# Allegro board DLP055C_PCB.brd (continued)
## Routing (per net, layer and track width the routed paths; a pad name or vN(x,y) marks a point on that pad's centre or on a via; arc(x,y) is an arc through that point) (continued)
P3P3V_SB: length 143.3
  TOP w0.203: U27.3 34.85,72.78 C530.2 ; U17.1 9.88,94.48 v1(9.54,94.82) ; U562.23 26.33,74.76 26.54,74.56 v1(26.67,74.56) ; U561.7 33.51,83.57 33.36,83.72 v1(33.25,83.72) ; U561.3 39.23,84.07 v1(39.26,84.05) ; U27.7 40.31,73.27 v1(40.38,73.35) ; U525.1 84.51,97.5 v1(83.96,98.04) ; v1(17.84,101.22) 16.83,101.22 16.58,101.47 U559.7
  TOP w0.254: v1(25.13,111.28) 25.47,110.94 U26.50 ; v1(25.62,120.98) 25.47,121.13 U26.11 ; U562.1 v1(27.61,80.65) ; U26.18 v1(21.97,121.14)
  TOP w0.381: R623.2 v1(40.84,82.74) ; v1(167.31,50.66) 167.45,50.8 R76.2 ; D52.2 v1(4.95,128.23) ; v1(77.15,146.66) U519.3 ; v1(33.86,72.5) 33.87,72.51 C530.2 ; R611.2 v1(11.11,119.38) ; U2.5 v1(61.38,137.16) ; R607.1 v1(42.58,99.51) ; R861.2 9.7,95.89 v1(9.11,95.89) ; U563.5 33.35,81.29 v1(33.59,81.05) ; D5.2 v1(104.35,38.42) ; D10.2 v1(40.49,90.77) ; v1(81.52,93.1) 81.52,92.96 82.07,92.42 U526.1 ; U19.5 v1(98.61,35.57) ; v1(34.72,75.2) 35.29,75.77 U560.8 ; R610.2 v1(11.11,116.84) ; R862.2 v1(8.94,97.27) ; R153.1 v1(91.96,31.75) ; R598.2 v1(11.11,118.11) ; U20.5 v1(98.61,31.45) ; U42.5 v1(41.86,90.79) ; U564.5 v1(41.99,83.17) ; U33.5 165.45,51.43 v1(165.44,51.44) ; U526.4 81.87,90.46 v1(81.39,89.99) ; R597.2 v1(11.11,115.57) ; D8.2 v1(104.33,30.16) ; U13.5 v1(92.58,29.54) ; R606.1 v1(42.58,103.53) ; U565.5 v1(59.06,148.83) ; U40.5 v1(41.7,86.98) ; U18.5 v1(86.25,29.86) ; v1(161.63,49.17) 161.63,49.18 R75.1 ; U3.5 v1(73.52,137.16) ; U14.5 v1(98.6,39.7) ; D7.2 v1(104.31,34.29) ; R832.1 v1(91.33,98.6) ; R609.2 v1(11.11,114.3) ; F1.2 v1(9.84,99.75) ; R1.2 v1(74.7,148.59) ; R596.2 v1(11.11,113.03) ; D53.2 v1(40.49,87.01)
  TOP w0.635: 167.42,134.52 TP248.1 168.49,134.52
  LY7_PLANE w0.635: 6.84,148.41 J85.1 ; J85.1 9.03,146.23 ; J85.1 9.03,148.41 ; J85.1 6.84,146.23 ; J96.1 43.32,94.16 ; J96.1 41.13,94.16 ; J96.1 43.32,96.34 ; J96.1 41.13,96.34 ; 11.49,101.86 J52.1 ; J52.1 13.28,101.86 ; J52.1 11.49,100.07 ; J52.1 13.28,100.07 ; TP248.1 168.49,134.52 ; TP248.1 167.42,134.52 ; TP248.1 168.49,133.45 ; TP248.1 167.42,133.45 ; J72.1 31.69,73.92 ; J72.1 31.69,72.13 ; J72.1 29.9,72.13 ; J72.1 29.9,73.92
  BOTTOM w0.203: C515.1 17.09,101.22 v1(17.84,101.22) ; v1(40.38,73.35) 40.3,73.35 40.04,73.61 39.62,73.61 C529.1
  BOTTOM w0.254: v1(25.13,111.28) 25.13,110.43 C519.1
  BOTTOM w0.381: U520.5 v1(78.1,146.83) ; U569.5 v1(70.36,150.13) ; v1(70.36,150.13) 74.38,150.13 74.7,149.82 v1(74.7,148.59) ; v1(70.36,150.13) 70.12,150.38 66.67,150.38 v1(66.45,150.16) U568.5 ; U58.5 v1(82.55,110.61) ; v1(26.67,74.56) 26.47,74.76 C622.1 ; v1(33.25,83.72) 33.35,83.82 C548.2 ; R605.2 v1(33.97,81.92) ; R196.2 86.47,89.97 86.09,89.59 v1(85.69,89.59) ; v1(27.61,80.65) 27.6,80.64 C623.1 ; U529.5 v1(84.69,112.31) ; U558.5 v1(23.1,117.09) ; R195.2 v1(91.1,93.34) ; v1(91.33,98.6) 91.33,98.17 90.94,97.79 R193.2 ; v1(76.06,136.02) 76.05,136 R87.1 ; C549.1 21.97,121.97 v1(21.97,121.14) ; R853.2 v1(41.71,127.29) ; C547.1 39.03,83.82 v1(39.26,84.05) ; R855.2 v1(32.82,125.53) ; R592.1 v1(43.21,114.22) ; C520.2 25.62,121.93 v1(25.62,120.98) ; R854.2 v1(38.53,127.39) ; R197.2 v1(87.19,96.72) ; R628.2 v1(12.5,139.81) ; C528.2 v1(34.72,75.2) ; v1(6.76,118.51) 6.65,118.51 6.41,118.75 R612.1
  BOTTOM w0.508: v1(74.7,148.59) 72.83,146.73 72.83,137.85 v1(73.52,137.16)
  vias: v1(81.29,118.92) v1(81.29,117.91) v1(81.29,116.89) v1(81.29,115.87) v1(82.31,118.92) v1(82.31,117.91) v1(82.31,116.89) v1(82.31,115.87) v1(83.32,118.92) v1(83.32,117.91) v1(83.32,116.89) v1(83.32,115.87) v1(84.34,118.92) v1(84.34,117.91) v1(84.34,116.89) v1(84.34,115.87) v1(85.36,118.92) v1(85.36,117.91) v1(85.36,116.89) v1(85.36,115.87) v1(86.37,118.92) v1(86.37,117.91) v1(86.37,116.89) v1(86.37,115.87) v1(167.32,135.59) v1(168.82,136.19) v1(168.77,135.38)
P4.0: length 7
  TOP w0.191: U26.45 22.97,106.32 22.35,105.7 22.35,104.1 22.54,103.9 TP116.1
P4.3: length 5.3
  TOP w0.191: U26.48 24.47,106.07 TP117.1
P4.4: length 7.3
  TOP w0.191: TP118.1 24.41,102.91 24.41,105.11 25.97,106.67 U26.51
P4.5: length 5.3
  TOP w0.191: U26.52 26.47,106.16 TP119.1
P4.6: length 6.9
  TOP w0.191: U26.53 26.97,105.78 26.35,105.16 TP120.1
P4.7: length 4.9
  TOP w0.191: U26.54 27.47,105.26 TP121.1
P5.0: length 5.3
  TOP w0.191: TP267.1 25.81,125.64 26.16,125.64 26.67,125.13 26.67,124.09 26.47,123.89 U26.9
P5.1: length 7.3
  TOP w0.191: TP37.1 21.92,127.01 23.39,127.01 25.19,125.21 25.95,125.21 26.26,124.9 26.26,124.21 25.97,123.92 U26.10
P5.2: length 9.8
  TOP w0.191: U26.69 33.45,115.46 TP75.1
P5.3: length 9.3
  TOP w0.191: TP71.1 39.65,111.16 38.3,111.16 38.07,111.39 38.04,111.39 33.47,115.96 U26.70
P5.4: length 7.8
  TOP w0.191: U26.12 24.97,124.82 23.41,126.37 23.35,126.37 23.29,126.44 20.57,126.44 TP36.1
P5.5: length 8.9
  TOP w0.191: TP35.1 18.37,126.09 23.15,126.09 24.16,125.09 24.16,125.09 24.44,124.81 24.44,124.8 24.47,124.77 24.47,124.72 24.47,124.72 24.47,124.3 24.47,124.3 U26.13
P5.6: length 6.7
  TOP w0.191: TP122.1 27.97,103.16 U26.55
P6.0: length 9.4
  TOP w0.191: TP74.1 35.61,118.37 34.64,118.37 33.56,119.46 U26.77
P6.1: length 8.8
  TOP w0.191: U26.78 33.59,119.95 34.64,118.91 36.99,118.91 TP70.1
P6.2: length 8.2
  TOP w0.191: TP73.1 37.75,120.05 34.06,120.05 33.65,120.45 U26.79
P6.3: length 7.7
  TOP w0.191: TP69.1 39.2,120.51 34.24,120.51 33.79,120.95 U26.80
P6.4: length 16.2
  TOP w0.191: U26.1 32.64,122.91 34.71,120.85 38.11,120.85 38.91,121.65 41.32,121.65 J57.1
  BOTTOM w0.191: R593.2 J57.1
P6.4_PU: length 2.6
  BOTTOM w0.191: R853.1 42.75,125.84 J57.2
P6.5: length 15.9
  TOP w0.191: J56.1 38.2,121.7 35.53,121.7 33.07,124.16 30.25,124.16 29.97,123.88 U26.2
  BOTTOM w0.191: J56.1 37.78,121.28 R594.2
P6.5_PU: length 2.6
  BOTTOM w0.191: J56.2 39.57,125.84 R854.1
P6.6: length 11.9
  TOP w0.191: J55.1 35.13,124.57 29.84,124.57 29.47,124.2 U26.3
  BOTTOM w0.191: R595.2 35.76,122.44 J55.1
P6.6_PU: length 2.9
  BOTTOM w0.191: R855.1 34.49,125.73 J55.2
P6.7: length 7.9
  TOP w0.191: U26.4 28.97,124.41 29.51,124.95 33.6,124.95 33.98,125.33 33.98,126.36 TP43.1
P7.0: length 6.1
  TOP w0.191: TP42.1 31.52,125.82 29.49,125.82 28.47,124.8 U26.5
P7.1: length 5
  TOP w0.191: U26.6 27.97,124.81 TP41.1
P7.2: length 4.4
  TOP w0.191: TP265.1 27.47,126.21 U26.7
P7.3: length 4.4
  TOP w0.191: TP266.1 26.97,126.39 26.97,125.31 27.01,125.27 27.01,123.95 26.97,123.9 U26.8
P7.4: length 4.8
  TOP w0.191: TP123.1 28.97,104.85 U26.57
P7.5: length 6.9
  TOP w0.191: TP124.1 29.47,103.57 U26.58
P7.6: length 5.1
  TOP w0.191: TP125.1 29.97,105.61 U26.59
P7.7: length 7.3
  TOP w0.191: TP126.1 32.05,102.89 32.05,106.71 30.47,108.3 U26.60
P8.0: length 9.8
  TOP w0.191: U26.15 23.47,124.3 23.47,124.3 23.47,124.72 23.47,124.72 22.48,125.71 16.84,125.71 TP34.1
P8.1: length 11.1
  TOP w0.191: U26.16 22.97,124.54 22.13,125.37 16.7,125.37 16.69,125.38 15.27,125.38 TP33.1
P8.2: length 12.4
  TOP w0.191: TP32.1 13.72,125.03 21.94,125.03 22.47,124.5 U26.17
PAUX0: length 18.5
  TOP w0.191: U15.AB5 v1(158.45,77.9)
  LY3 w0.076: 153.95,77.05 153.68,77.31 153.62,77.31 153.62,77.31 153.28,77.31 153.28,77.31 152.62,77.31 152.62,77.31 152.28,77.31 152.28,77.31 151.62,77.31 151.62,77.31 151.28,77.31 151.04,77.07 151.03,77.04 151.03,76.65 151.2,76.49
  LY3 w0.102: v1(158.45,77.9) 157.97,78.38 156.1,78.38 155.92,78.2 155.92,76.53 155.78,76.39 154.27,76.39 153.95,76.72 153.95,77.05 ; v1(149.44,73.89) 149.46,73.91 150.1,73.91 151.2,75.01 151.2,76.49
  BOTTOM w0.191: R261.2 151.07,75.5 151.07,75.22 R260.2 150.53,74.03 150.39,73.89 v1(149.44,73.89)
PAUX7: length 6.5
  TOP w0.191: U15.AA2 157.48,74.86 157.48,73.1 158.09,72.49 158.09,70.55 158.33,70.32 158.59,70.32 158.68,70.23 R674.2
PAUX8: length 4.6
  TOP w0.191: U15.AA1 156.95,73 157.4,72.55 R235.2
PAUX9: length 10.5
  TOP w0.191: R234.2 155.9,69.08 155.9,69.86 v1(155.98,69.94) ; U15.Y5 v1(156.45,77.9)
  BOTTOM w0.191: v1(156.45,77.9) 156.93,77.42 156.93,75.51 157.07,75.37 157.07,73.2 157.08,73.2 157.08,72.88 157.1,72.85 157.1,72.83 157.34,72.59 157.34,72.28 157.37,72.25 157.37,71.84 157.34,71.81 157.34,71.3 v1(155.98,69.94)
PDATA_C0: length 134.7
  TOP w0.185: J44.24 v1(99.65,10.47)
  TOP w0.381: U15.A10 v1(136.45,82.9)
  LY3 w0.122: v1(136.45,82.9) 135.41,82.9 135.17,83.14 134.62,83.14 134.13,83.63 134.09,83.63 134.07,83.66 134.05,83.66 133.88,83.83 117.91,83.83 117.61,83.52 111.4,83.52 110.31,84.62 110.31,85.91 109.34,86.88 100.17,86.88 99.51,86.22 v1(98.62,86.22)
  LY12 w0.122: v1(99.65,10.47) 99.65,10.51 100.91,11.77 103.73,11.77 104.49,12.53 104.49,15.53 103.98,16.04 102.08,16.04 101.75,16.37 99.44,16.37 97.38,18.42 97.38,28.63 101.49,32.75 101.49,60.18 103.17,61.86 103.17,64.35 97.41,70.11 97.41,85.4 98.22,86.22 v1(98.62,86.22)
PDATA_C1: length 140
  TOP w0.185: J44.23 v1(99.15,9.73)
  TOP w0.381: U15.B10 v1(137.45,82.9)
  LY3 w0.122: v1(137.45,82.9) 137.45,82.9 136.97,82.42 135.38,82.42 134.92,82.88 134.73,82.88 134.73,82.88 134.52,82.88 134.51,82.88 134.01,83.37 133.98,83.37 133.96,83.4 133.94,83.4 133.77,83.57 118.02,83.57 117.71,83.26 111.08,83.26 109.85,84.49 109.85,85.84 109.07,86.62 101.16,86.62 100.43,85.89 99.16,85.89 98.9,85.63 v1(98.9,85.03)
  LY12 w0.122: v1(99.15,9.73) 99.68,9.73 100.85,10.89 105.34,10.89 106.93,12.48 106.93,16.11 106.65,16.39 103.76,16.39 103.48,16.67 99.82,16.67 97.76,18.73 97.76,28.36 101.85,32.44 101.85,59.9 103.45,61.5 103.45,64.61 97.81,70.24 97.81,84.54 98.3,85.03 v1(98.9,85.03)
PDATA_C2: length 133.3
  TOP w0.185: J44.21 v1(98.15,10.53)
  TOP w0.381: U15.C11 v1(138.45,83.9)
  LY3 w0.122: v1(138.45,83.9) 138.45,83.85 137.95,83.35 137.95,81.66 137.71,81.42 136.24,81.42 135.83,81.84 135.44,81.84 135.24,82.04 134.58,82.04 133.38,80.84 131.36,80.84 128.99,83.2 118.02,83.2 117.69,82.86 111.05,82.86 110.71,83.2 110.25,83.2 109.52,83.93 109.52,85.61 108.79,86.34 101.8,86.34 99.64,84.18 v1(95.93,84.18)
  LY12 w0.122: v1(95.93,84.18) 95.42,83.68 95.42,63.33 100.78,57.97 100.78,34.38 96.47,30.06 96.47,18.37 99.67,15.17 99.67,14.44 99.62,14.4 99.62,13.54 99.67,13.5 99.67,12.12 98.15,10.61 v1(98.15,10.53)
PDATA_C3: length 133.9
  TOP w0.185: J44.20 v1(97.65,9.86)
  TOP w0.381: U15.D11 v1(139.45,83.9)
  LY3 w0.122: v1(96.8,86.09) 97.94,87.23 112.87,87.23 113.43,86.67 118.24,86.67 120.82,84.09 133.99,84.09 134.16,83.92 134.18,83.92 134.2,83.9 134.24,83.9 134.69,83.45 137.69,83.45 137.92,83.68 137.92,84.18 138.15,84.41 138.93,84.41 v1(139.45,83.9)
  LY12 w0.122: v1(96.8,86.09) 96.8,62.39 101.14,58.05 101.14,33.04 96.95,28.85 96.95,18.47 99.32,16.09 101.06,16.09 101.98,15.17 101.98,13.09 101.09,12.2 100.66,12.2 98.29,9.84 97.66,9.84 v1(97.65,9.86)
PDATA_C4: length 130.3
  TOP w0.185: J44.18 v1(96.65,10.35)
  TOP w0.381: U15.A12 v1(136.45,84.9)
  LY3 w0.122: v1(95.2,86.98) 95.2,87.74 96.49,89.04 102.23,89.04 102.71,88.55 117.37,88.55 121.13,84.79 134.03,84.79 134.38,84.44 134.39,84.44 134.42,84.42 135.13,84.42 135.61,84.9 v1(136.45,84.9)
  LY12 w0.122: v1(95.2,86.98) 95.2,84.84 94.6,84.25 94.6,63.24 100.12,57.72 100.12,38.92 95.5,34.3 95.5,29.52 94.99,29.02 94.99,17.79 96.87,15.91 96.87,11.13 96.65,10.91 v1(96.65,10.35)
PDATA_C5: length 131.6
  TOP w0.185: J44.17 v1(96.15,9.63)
  TOP w0.381: U15.B12 v1(137.45,84.9)
  LY3 w0.122: v1(137.45,84.9) 136.96,84.41 135.88,84.41 135.62,84.16 134.31,84.16 134.28,84.18 134.27,84.18 134.04,84.41 120.93,84.41 117.05,88.29 102.55,88.29 101.98,87.72 97.18,87.72 v1(96.47,87)
  LY12 w0.122: v1(96.47,87) 96.47,86.46 95.91,85.9 95.91,85.02 94.92,84.03 94.92,63.41 100.43,57.9 100.43,34.78 95.89,30.24 95.89,18.34 99.35,14.88 99.35,13.43 99.36,13.42 99.36,12.53 97.12,10.29 97.12,9.98 96.77,9.63 v1(96.15,9.63)
PDATA_C6: length 139.1
  TOP w0.185: J44.15 v1(95.15,11.39)
  TOP w0.381: U15.C13 v1(138.45,85.9)
  LY3 w0.076: v1(138.45,85.9) 138.03,85.49 136.14,85.49 136.07,85.56 135.88,85.56
  LY3 w0.122: 135.88,85.56 135.3,85.56 135.17,85.68 135.17,85.99 134.71,86.45 130.28,86.45 129.61,85.78 128.95,85.78 128.8,85.63 128.19,85.63 128.17,85.65 124.89,85.65 124.87,85.63 124.26,85.63 124.24,85.65 121.64,85.65 119.6,87.7 119.6,87.85 118.22,89.22 110.49,89.22 110.41,89.31 105.2,89.31 104.6,89.91 95.13,89.91 94.28,89.06 94.28,86.06 v1(93.68,85.46)
  LY12 w0.122: v1(95.15,11.39) 94.06,12.48 92.78,12.48 91.87,13.39 91.87,14.98 90.29,16.55 90.29,19.4 91.17,20.28 91.17,27.28 90.9,27.56 90.9,39.63 99.17,47.9 99.17,57.33 93.34,63.15 93.34,85.12 v1(93.68,85.46)
PDATA_C7: length 139
  TOP w0.185: J44.14 v1(94.65,9.54)
  TOP w0.381: U15.D13 v1(139.45,85.9)
  LY3 w0.076: 135.88,85.29 136.26,85.29 136.28,85.31 138.28,85.31 138.35,85.39 138.94,85.39 v1(139.45,85.9)
  LY3 w0.122: v1(94.81,88.32) 95.79,89.3 102.34,89.3 102.78,88.86 117.55,88.86 121.01,85.39 124.13,85.39 124.15,85.37 124.97,85.37 125,85.39 128.06,85.39 128.08,85.37 128.91,85.37 128.97,85.43 135.06,85.43 135.19,85.29 135.88,85.29
  LY12 w0.122: v1(94.65,9.54) 96.6,11.49 96.6,15.22 95.88,15.93 93.06,15.93 92.38,16.62 92.38,25.36 91.49,26.25 91.49,39.31 99.44,47.26 99.44,57.56 93.83,63.17 93.83,84.73 94.2,85.11 94.2,87.71 v1(94.81,88.32)
PDATA_C8: length 140.4
  TOP w0.185: J44.12 93.65,9.41
  TOP w0.191: 93.65,9.41 94.42,10.19 v1(94.42,10.69)
  TOP w0.381: U15.A14 v1(136.45,86.9)
  LY3 w0.122: v1(92.86,86.88) 93.56,87.58 93.56,89.08 94.92,90.43 105.36,90.43 105.84,89.95 110.23,89.95 110.32,90.04 110.73,90.45 111.85,90.45 112.22,90.19 112.67,89.75 118.49,89.75 120.12,88.12 120.12,87.91 121.23,86.8 124.34,86.8 124.37,86.83 124.76,86.83 124.78,86.8 128.22,86.8 128.24,86.82 128.3,86.82 128.3,86.83 128.69,86.83 128.72,86.8 128.9,86.8 129.31,87.21 134.74,87.21 135.4,86.55 135.42,86.55 135.45,86.53 135.84,86.53 135.86,86.55 135.88,86.55 135.95,86.62 136.14,86.62 136.42,86.9 v1(136.45,86.9)
  LY12 w0.122: v1(94.42,10.69) 94.42,10.64 93.54,9.76 91.77,9.76 90.95,10.58 90.95,11.44 89.38,13.01 89.38,19.26 89.79,19.67 89.79,40.73 98.62,49.56 98.62,57.01 92.5,63.12 92.5,86.52 v1(92.86,86.88)
PDATA_C9: length 138.7
  TOP w0.185: J44.11 93.15,9.54
  TOP w0.191: 93.15,9.54 93.79,10.19 v1(93.79,11.25)
  TOP w0.381: U15.B14 v1(137.45,86.9)
  LY3 w0.122: v1(137.45,86.9) 137.43,86.9 136.93,86.39 136.07,86.39 135.94,86.27 135.34,86.27 135.31,86.29 135.29,86.29 134.63,86.95 129.65,86.95 128.96,86.26 128.96,86.17 128.69,85.89 128.3,85.89 128.28,85.92 128.25,85.92 127.63,86.54 125.94,86.54 125.32,85.92 124.78,85.92 124.76,85.89 124.37,85.89 124.34,85.92 121.74,85.92 119.86,87.81 119.86,87.97 118.34,89.49 112.56,89.49 112.13,89.92 111.89,89.92 111.62,90.19 110.84,90.19 110.34,89.69 105.52,89.69 105.03,90.17 95.02,90.17 93.86,89.01 93.86,87.19 93.67,86.99 v1(93.67,86.55)
  LY12 w0.122: v1(93.79,11.25) 93.79,11.27 93.24,11.82 92.78,11.82 91.49,13.12 91.49,13.52 91.51,13.54 91.51,14.94 89.96,16.49 89.96,19.46 90.06,19.55 90.06,39.88 98.89,48.72 98.89,57.12 92.96,63.06 92.96,85.84 v1(93.67,86.55)
PM0_BYTEZ: length 2.8
  TOP w0.191: v1(140.85,132.92) 141.11,133.18 U4.53
  BOTTOM w0.191: R89.1 141.17,133.24 v1(140.85,132.92)
PM0_RY_BYZ: length 2.3
  TOP w0.191: TP8.1 164.13,139.68 U4.17
PM0_WPZ: length 2.4
  TOP w0.191: U4.16 160.52,139.18 v1(160.52,139.18)
  BOTTOM w0.191: v1(160.52,139.18) R85.2
PM1_BYTEZ: length 2.2
  TOP w0.191: U8.53 v1(141.02,115.08)
  BOTTOM w0.191: R102.1 141.17,115.14 141.11,115.08 v1(141.02,115.08)
PM1_RY_BYZ: length 2.3
  TOP w0.191: TP12.1 164.13,121.58 U8.17
PM1_WPZ: length 2.4
  TOP w0.191: U8.16 v1(160.54,121.08)
  BOTTOM w0.191: v1(160.54,121.08) 160.61,121.08 R92.2
PM_ADDR_0: length 51
  TOP w0.191: U8.31 v1(141.02,126.08) ; U15.T30 v1(152.45,103.9) ; v1(140.98,144.18) U4.31
  LY3 w0.122: v1(141.02,126.08) 141.02,126.18 137.95,129.24 137.95,141.15 v1(140.98,144.18)
  LY12 w0.122: v1(141.02,126.08) 141.11,126.08 143.12,124.08 143.12,114.93 150.87,107.17 150.87,105.96 152.45,104.39 v1(152.45,103.9)
PM_ADDR_1: length 54.9
  TOP w0.191: U15.U26 v1(153.45,99.9) ; v1(160.52,144.18) U4.26 ; U8.26 v1(160.38,126.08)
  LY3 w0.076: 153.05,104.46 153.03,104.44 153.03,100.31
  LY3 w0.102: v1(153.45,99.9) 153.03,100.31
  LY3 w0.122: 153.05,104.46 153.05,110.95 153.36,111.26 153.36,113.37 153.13,113.59 153.13,118.6 160.38,125.85 v1(160.38,126.08) 158.96,126.08 156.96,128.09 156.96,140.61 v1(160.52,144.18)
PM_ADDR_2: length 58.2
  TOP w0.191: U8.25 v1(164.3,125.58) ; U15.U27 v1(153.45,100.9) ; U4.25 v1(163.18,143.68)
  LY3 w0.122: v1(163.18,143.68) 161.35,141.85 161.35,136.98 160.47,136.1 160.47,132.21 160.59,132.1 160.59,131.55 164.3,127.84 v1(164.3,125.58)
  LY12 w0.076: 153.03,103.47 153.03,104.44 153.05,104.46
  LY12 w0.102: 153.03,103.47 152.94,103.37 152.94,101.41 v1(153.45,100.9)
  LY12 w0.122: 153.05,104.46 153.05,110.62 151.97,111.7 151.97,115.47 153.05,116.56 153.05,118.48 160.16,125.58 v1(164.3,125.58)
PM_ADDR_3: length 51.2
  TOP w0.191: v1(160.57,143.18) U4.24 ; U8.24 v1(160.47,125.08) ; U15.U29 v1(153.45,102.9)
  LY3 w0.076: 153.84,104.46 153.86,104.44 153.86,103.31 v1(153.45,102.9)
  LY3 w0.122: v1(160.57,143.18) 160.57,143.14 157.22,139.79 157.22,128.28 158.95,126.55 160.77,126.55 161.06,126.27 161.06,125.53 160.61,125.08 v1(160.47,125.08) 153.46,118.07 153.46,114.34 153.84,113.96 153.84,104.46
PM_ADDR_4: length 53.2
  TOP w0.191: U8.23 v1(164.3,124.58) ; U4.23 v1(163.27,142.68) ; U15.U30 v1(153.45,103.9)
  LY3 w0.122: v1(164.3,124.58) 164.79,125.08 164.79,127.74 160.88,131.65 160.88,135.9 161.62,136.64 161.62,141.03 v1(163.27,142.68)
  LY12 w0.122: v1(164.3,124.58) 159.96,124.58 153.45,118.07 v1(153.45,103.9)
PM_ADDR_5: length 50
  TOP w0.191: v1(160.57,142.18) U4.22 ; U8.22 v1(160.47,124.08) ; U15.V29 v1(154.45,102.9)
  LY3 w0.076: v1(154.45,102.9) 154.03,103.31 154.03,104.2 154.11,104.28 154.11,104.46
  LY3 w0.122: 154.11,104.46 154.11,114.89 153.81,115.2 153.81,117.42 v1(160.47,124.08) 160.61,124.08 161.32,124.79 161.32,126.4 160.86,126.86 159.18,126.86 157.49,128.55 157.49,139.06 160.57,142.14 v1(160.57,142.18)
PM_ADDR_6: length 54.5
  TOP w0.191: U15.V28 v1(154.45,101.9) ; U8.21 v1(164.3,123.58) ; U4.21 v1(163.33,141.68)
  LY3 w0.122: v1(163.33,141.68) 161.88,140.23 161.88,136.32 161.16,135.59 161.16,131.77 165.06,127.87 165.06,124.34 v1(164.3,123.58)
  LY12 w0.122: v1(164.3,123.58) 159.99,123.58 153.78,117.38 153.78,115.43 154.05,115.16 154.05,104.46 153.97,104.38 153.97,102.37 v1(154.45,101.9)
PM_ADDR_7: length 50.6
  TOP w0.191: U8.20 v1(160.5,123.08) ; U15.V27 v1(154.45,100.9) ; v1(160.55,141.18) U4.20
  LY3 w0.076: 154.84,104.46 154.86,104.44 154.86,101.31 v1(154.45,100.9)
  LY3 w0.122: 154.84,104.46 154.84,117.75 160.17,123.08 v1(160.5,123.08) 160.61,123.08 161.59,124.06 161.59,126.52 160.98,127.14 159.36,127.14 157.76,128.74 157.76,138.43 160.5,141.18 v1(160.55,141.18)
PM_ADDR_8: length 50.8
  TOP w0.191: U15.V26 v1(154.45,99.9) ; U4.10 159.97,136.18 v1(159.74,135.95) ; U8.10 v1(160.57,118.08)
  LY3 w0.076: 155.03,100.49 155.03,103.28 155.16,103.4 155.69,103.4 155.95,103.66 ; 157.86,104.44 157.86,104.07 157.86,104.07 157.86,103.72 157.64,103.5 157.63,103.5 157.62,103.49 157.28,103.49 157.26,103.5 157.21,103.5 156.99,103.71
  LY3 w0.102: 156.99,103.71 156.99,104.07 156.66,104.4 156.24,104.4 155.95,104.11 155.95,103.66 ; 155.03,100.49 v1(154.45,99.9)
  LY3 w0.122: 157.86,104.44 155.98,106.32 155.98,114.88 156.99,115.88 157.98,115.88 160.18,118.08 v1(160.57,118.08) 160.61,118.12 160.61,118.77 162.66,120.81 162.66,127.04 158.82,130.87 158.82,135.47 159.3,135.95 v1(159.74,135.95)
PM_ADDR_9: length 45.2
  TOP w0.191: U15.W30 v1(155.45,103.9) ; v1(163.5,135.77) 163.4,135.68 U4.9 ; U8.9 v1(163.26,117.58)
  LY3 w0.122: v1(163.5,135.77) 163.5,135.64 163.22,135.37 163.22,135.36 163.22,134.81 162.68,134.27 162.68,132.22 166.34,128.56 166.34,128.47 166.39,128.42 166.39,119.68 164.3,117.58 v1(163.26,117.58)
  LY12 w0.122: v1(163.26,117.58) 159.58,117.58 157.11,115.11 157.11,114.47 156.84,114.19 156.19,114.19 155.45,113.45 v1(155.45,103.9)
PM_ADDR_10: length 44
  TOP w0.191: v1(159.76,134.73) 160.21,135.18 U4.8 ; U15.W29 v1(155.45,102.9) ; U8.8 v1(160.51,117.08)
  LY3 w0.076: 158.11,104.24 158.03,104.16 158.03,104.14 158.03,103.64 157.71,103.31 157.01,103.31 156.84,103.49 156.62,103.49 156.62,103.49 156.28,103.49 156.27,103.49 156.04,103.49 v1(155.45,102.9)
  LY3 w0.122: 158.11,104.24 158.11,104.92 156.46,106.57 156.46,113.04 v1(160.51,117.08) 160.61,117.08 161.08,117.55 161.08,118.84 162.92,120.68 162.92,127.17 159.09,131 159.09,134.54 159.28,134.73 v1(159.76,134.73)
PM_ADDR_11: length 45.7
  TOP w0.191: U4.7 v1(163.72,134.68) ; U15.W28 v1(155.45,101.9) ; U8.7 v1(163.15,116.58)
  LY3 w0.122: v1(163.72,134.68) 163.48,134.44 163.48,134.41 162.99,133.92 162.99,132.31 166.61,128.69 166.61,128.58 166.66,128.53 166.66,118.94 164.3,116.58 v1(163.15,116.58)
  LY12 w0.122: v1(163.15,116.58) 160.04,116.58 155.94,112.48 155.94,102.4 v1(155.45,101.9)
PM_ADDR_12: length 45.5
  TOP w0.191: U4.6 160.28,134.18 159.98,133.88 v1(159.94,133.88) ; U8.6 v1(160.54,116.08) ; U15.W26 v1(155.45,99.9)
  LY3 w0.076: 158.99,104.46 158.99,103.85 158.63,103.49 158.19,103.49 157.85,103.14 157.85,103.08 157.86,103.07 157.86,102.73 157.62,102.49 157.28,102.49 157.26,102.51 157.21,102.51 156.92,102.79 156.92,103.08 156.71,103.3 156.63,103.3 156.62,103.31 156.28,103.31 156.26,103.3 156.16,103.3 155.89,103.03
  LY3 w0.102: v1(155.45,99.9) 155.89,100.34 155.89,103.03
  LY3 w0.122: 158.99,104.46 158.99,114.54 v1(160.54,116.08) 161.36,116.91 161.36,118.71 163.19,120.54 163.19,127.3 159.36,131.13 159.36,132.92 159.94,133.51 v1(159.94,133.88)
PM_ADDR_13: length 41.1
  TOP w0.191: U4.5 v1(163.87,133.68) ; U8.5 v1(163.17,115.58) ; U15.Y30 v1(156.45,103.9)
  LY3 w0.122: v1(163.17,115.58) 164.3,115.58 165.63,116.91 165.63,117.36 166.93,118.66 166.93,128.64 166.87,128.69 166.87,128.82 163.32,132.38 163.32,133.13 v1(163.87,133.68)
  LY12 w0.122: v1(156.45,103.9) 156.45,107.83 157.99,109.38 158.34,109.38 159.12,110.16 159.12,111.77 161.97,114.62 161.97,114.96 162.59,115.58 v1(163.17,115.58)
PM_ADDR_14: length 41.1
  TOP w0.191: U15.Y29 v1(156.45,102.9) ; U4.4 160.37,133.18 v1(159.99,132.8) ; U8.4 v1(160.52,115.08)
  LY3 w0.076: 157.03,102.31 157.7,102.31 158.03,102.64 158.03,103.07 158.28,103.31 158.74,103.31 159.61,104.18 159.61,104.46
  LY3 w0.102: v1(156.45,102.9) 157.03,102.31
  LY3 w0.122: v1(159.99,132.8) 159.62,132.43 159.62,131.26 163.46,127.42 163.46,120.41 161.66,118.61 161.66,116.13 160.61,115.08 v1(160.52,115.08) 159.3,113.86 159.3,109.02 159.72,108.61 159.72,106.21 160.08,105.84 160.08,104.93 159.61,104.46
PM_ADDR_15: length 45.6
  TOP w0.191: U4.3 v1(163.86,132.68) ; U15.Y28 v1(156.45,101.9) ; U8.3 v1(163.64,114.58)
  LY3 w0.122: v1(163.86,132.68) 164.19,132.68 167.14,129.73 167.14,128.8 167.19,128.75 167.19,118.55 166.99,118.34 166.98,118.34 165.89,117.25 165.89,116.18 164.3,114.58 v1(163.64,114.58)
  LY12 w0.076: 157.59,102.34 157.86,102.6 157.86,103.66 157.86,104.18 157.58,104.46
  LY12 w0.102: 157.59,102.34 156.88,102.34 v1(156.45,101.9)
  LY12 w0.122: 157.58,104.46 157.1,104.94 157.1,106.99 157.93,107.82 160.25,107.82 162,109.57 163.61,109.57 164.3,110.26 164.3,113.92 v1(163.64,114.58)
PM_ADDR_16: length 56.1
  TOP w0.191: U8.54 v1(144.5,114.58) ; U15.Y27 v1(156.45,100.9) ; v1(146.12,132.68) U4.54
  LY12 w0.076: 152.66,103.44 152.86,103.64 152.86,104.15 152.7,104.31
  LY12 w0.102: v1(156.45,100.9) 156.89,100.46 157.72,100.46 158,100.18 158,99.67 157.7,99.36 152.07,99.36 151.82,99.61 151.82,103.19 152.06,103.44 152.66,103.44
  LY12 w0.122: 144.51,114.58 146.16,112.93 148.37,112.93 150.95,110.34 150.95,108.16 151.15,107.97 151.15,106.35 152.7,104.79 152.7,104.31 ; 144.51,114.58 147.81,117.88 147.81,130.99 v1(146.12,132.68) ; 144.51,114.58 v1(144.5,114.58)
PM_ADDR_17: length 56
  TOP w0.191: U8.19 v1(164.3,122.58) ; U15.Y26 v1(156.45,99.9) ; U4.19 v1(163.39,140.68)
  LY3 w0.122: v1(164.3,122.58) 165.33,123.61 165.33,127.98 165.27,128.03 165.27,128.05 161.46,131.86 161.46,135.34 162.15,136.03 162.15,139.44 v1(163.39,140.68)
  LY12 w0.076: 154.77,104.3 154.86,104.21 154.86,101.33
  LY12 w0.102: 154.86,101.33 154.95,101.24 154.95,100.55 155.12,100.38 155.97,100.38 v1(156.45,99.9)
  LY12 w0.122: 154.77,104.3 154.77,117.35 160,122.58 160.06,122.58 160.07,122.59 160.46,122.59 160.46,122.58 v1(164.3,122.58)
PM_ADDR_18: length 48.8
  TOP w0.191: v1(159.68,121.12) 160.14,121.58 160.38,121.58 160.45,121.65 160.51,121.65 160.79,121.93 160.79,121.99 160.88,122.08 U8.18 ; U4.18 160.84,140.18 160.79,140.13 160.79,140.02 160.51,139.74 160.51,139.74 160.46,139.7 160.11,139.7 v1(159.58,139.18) ; U15.AA30 v1(157.45,103.9)
  LY3 w0.122: v1(157.45,103.9) 157.45,104.46 155.27,106.64 155.27,117.22 159.17,121.12 v1(159.68,121.12) 160.15,121.6 160.42,121.6 161.86,123.04 161.86,126.65 161.08,127.43 159.57,127.43 158.02,128.98 158.02,138.07 159.13,139.18 v1(159.58,139.18)
PM_ADDR_19: length 46.4
  TOP w0.191: U8.11 v1(164.3,118.58) ; U15.AA29 v1(157.45,102.9) ; U4.11 v1(163.34,136.68)
  LY3 w0.122: v1(163.34,136.68) 162.95,136.29 162.95,135.25 162.4,134.71 162.4,132.11 166.07,128.44 166.07,128.36 166.13,128.31 166.13,120.41 v1(164.3,118.58)
  LY12 w0.122: v1(157.45,102.9) 156.93,103.41 156.93,104.46 156.82,104.57 156.82,107.35 157.9,108.43 160.22,108.43 161.65,109.86 161.65,112.5 162.83,113.67 162.83,114.66 163.19,115.03 163.46,115.03 164.74,116.3 164.74,118.14 v1(164.3,118.58)
PM_ADDR_20: length 57.9
  TOP w0.191: v1(159.7,119.38) 160.65,119.38 160.95,119.08 U8.12 ; v1(159.56,136.99) 160.05,137.48 160.67,137.48 160.97,137.18 U4.12 ; U15.AA27 v1(157.45,100.9)
  LY3 w0.122: v1(159.7,119.38) 160.54,119.38 162.39,121.23 162.39,126.91 161.3,128 159.89,128 158.56,129.33 158.56,136.33 159.22,136.99 v1(159.56,136.99)
  LY12 w0.076: 158.03,101.49 158.03,104.07 158.04,104.08 158.04,104.46
  LY12 w0.102: v1(157.45,100.9) 158.03,101.49
  LY12 w0.122: 158.04,104.46 158.04,104.99 157.38,105.65 157.38,106.74 158.02,107.38 162.95,107.38 165.02,109.45 165.02,118.8 164.8,119.03 164.51,119.03 164.49,119.05 164.1,119.05 164.08,119.03 160.06,119.03 v1(159.7,119.38)
PM_ADDR_21: length 55.1
  TOP w0.191: U8.15 v1(164.3,120.58) ; U4.15 v1(163.31,138.68) ; U15.AA26 v1(157.45,99.9)
  LY3 w0.122: v1(163.31,138.68) 162.42,137.79 162.42,135.86 161.77,135.21 161.77,131.95 165.54,128.18 165.54,128.14 165.59,128.09 165.59,121.88 v1(164.3,120.58)
  LY12 w0.076: 155.05,104.46 155.03,104.44 155.03,101.65 155.26,101.42
  LY12 w0.102: 155.26,101.42 155.82,101.42 155.94,101.29 155.94,100.76 156.27,100.44 156.62,100.44 156.81,100.25 157.09,100.25 v1(157.45,99.9)
  LY12 w0.122: v1(164.3,120.58) 158.57,120.58 155.05,117.07 155.05,104.46
PM_ADDR_22: length 37.4
  TOP w0.191: v1(160.12,131.89) 160.41,132.18 U4.2 ; U8.2 v1(160.5,114.08) ; U15.AB29 v1(158.45,102.9)
  LY3 w0.076: 158.58,102.9 160.14,104.46
  LY3 w0.102: v1(158.45,102.9) 158.58,102.9
  LY3 w0.122: 160.61,114.08 161.38,113.32 161.38,109.18 160.76,108.56 160.76,105.08 160.14,104.46 ; 160.61,114.08 v1(160.5,114.08) ; 160.61,114.08 161.94,115.41 161.94,118.5 163.72,120.28 163.72,127.55 160.14,131.13 160.14,131.86 v1(160.12,131.89)
PM_ADDR_23: length 62
  TOP w0.191: v1(167.23,110.5) 166.34,111.39 165.98,111.39 163.79,113.57 163.78,113.57 163.77,113.58 163.73,113.58 163.73,113.59 163.45,113.59 163.45,113.58 163.24,113.58 U8.1 ; U15.AB28 v1(158.45,101.9) ; v1(167.36,131) 164.26,131 163.57,131.68 U4.1
  LY3 w0.122: v1(167.36,131) 167.36,130.34 167.64,130.06 167.64,127.14 168.93,125.84 168.93,120.84 171.29,118.47 174.62,118.47 175.36,117.74 175.36,113.7 172.16,110.5 v1(167.23,110.5) 166.54,109.81 164.92,109.81 164.38,109.27 164.38,105.23 163.9,104.74 163.16,104.74 162.99,104.57 162.99,101.69 162.71,101.41 158.95,101.41 158.46,101.9 v1(158.45,101.9)
PM_CSZ_0: length 53.9
  TOP w0.191: v1(145.94,143.71) 143.58,143.71 143.55,143.68 U4.32 ; U15.T27 v1(152.45,100.9)
  LY3 w0.076: 152.63,104.46 152.86,104.23 152.86,101.31 v1(152.45,100.9)
  LY3 w0.122: v1(145.94,143.71) 151.86,137.79 151.86,110.71 151.08,109.93 151.08,106.01 152.63,104.46
  BOTTOM w0.191: R84.2 v1(145.94,143.71)
PM_CSZ_1: length 31.9
  TOP w0.191: v1(144.45,125.62) 143.58,125.62 143.55,125.58 U8.32 ; U15.T28 v1(152.45,101.9)
  LY3 w0.122: v1(152.45,101.9) 151.96,102.38 151.96,104.66 150.82,105.81 150.82,110.04 150.84,110.05 150.84,119.91 145.13,125.62 v1(144.45,125.62)
  BOTTOM w0.191: R93.2 v1(144.45,125.62)
PM_DATA_0: length 52.9
  TOP w0.191: U8.35 141.05,124.08 v1(141.01,124.04) ; U4.35 141.11,142.18 v1(141.03,142.1) ; U15.L29 v1(146.45,102.9)
  LY3 w0.122: v1(141.01,124.04) 141.05,124.08 141.62,124.08 141.95,124.42 141.95,128.13 138.49,131.6 138.49,139.55 v1(141.03,142.1)
  LY12 w0.122: v1(141.01,124.04) 141.16,124.04 141.84,123.36 141.84,120.18 141.26,119.6 140.67,119.6 140.33,119.94 139.81,119.94 139.35,119.48 139.35,114.41 140.75,113 141.54,113 143.87,110.68 144.73,110.68 146.52,108.88 146.52,104.71 146.93,104.3 146.93,103.38 v1(146.45,102.9)
PM_DATA_1: length 54.8
  TOP w0.191: v1(140.02,122.56) 140.97,122.56 141.5,123.08 U8.37 ; U15.L30 v1(146.45,103.9) ; U4.37 v1(140.99,141.18)
  LY3 w0.122: v1(140.99,141.18) 138.75,138.94 138.75,131.72 142.22,128.26 142.22,123.98 140.79,122.56 v1(140.02,122.56)
  LY12 w0.122: v1(140.02,122.56) 141.27,122.56 141.56,122.27 141.56,120.9 141.26,120.6 139.93,120.6 138.86,119.53 138.86,111.26 139.41,110.71 143.1,110.71 143.62,110.19 144.73,110.19 146.23,108.69 146.23,104.6 146.45,104.39 v1(146.45,103.9)
PM_DATA_2: length 54.8
  TOP w0.191: U4.39 v1(141.03,140.18) ; U15.L28 v1(146.45,101.9) ; v1(140.93,121.97) 141.04,122.08 U8.39
  LY3 w0.122: v1(140.93,121.97) 141.01,121.97 142.48,123.45 142.48,128.39 139.02,131.85 139.02,138.17 v1(141.03,140.18)
  LY12 w0.122: v1(146.45,101.9) 146,102.35 145.11,102.35 143.81,103.65 143.81,105.63 145.01,106.83 145.01,108.64 144.24,109.41 142.95,109.41 142.64,109.71 138.27,109.71 137.97,110.02 137.97,119.88 140.07,121.97 v1(140.93,121.97)
PM_DATA_3: length 54.2
  TOP w0.191: U8.41 v1(140.92,121.08) ; U15.M27 v1(147.45,100.9) ; U4.41 v1(141.04,139.18)
  LY3 w0.122: v1(141.04,139.18) 140.59,139.18 139.29,137.87 139.29,131.98 142.75,128.52 142.75,122.07 141.77,121.08 v1(140.92,121.08)
  LY12 w0.122: v1(147.45,100.9) 146.93,101.42 146.93,102.17 146.7,102.4 146.26,102.4 145.99,102.67 145.99,104.1 145.03,105.07 145.03,106.17 145.29,106.43 145.29,109 144.5,109.79 143.36,109.79 142.93,110.22 139.03,110.22 138.43,110.83 138.43,119.63 139.88,121.08 v1(140.92,121.08)
PM_DATA_4: length 47.4
  TOP w0.191: U8.44 v1(144.4,119.58) ; U4.44 v1(145.91,137.68) ; U15.M28 v1(147.45,101.9)
  LY3 w0.122: v1(144.4,119.58) 144.4,118.88 143.25,117.72 143.25,113.76 145.01,112 145.01,105.14 145.96,104.19 145.96,103.45 146.05,103.37 146.61,103.37 146.91,103.07 146.91,102.44 v1(147.45,101.9)
  LY12 w0.122: v1(145.91,137.68) 144.63,136.4 144.63,132.15 146.69,130.09 146.69,121.18 145.1,119.58 v1(144.4,119.58)
PM_DATA_5: length 44.8
  TOP w0.191: U8.46 v1(144.77,118.58) ; U15.M29 v1(147.45,102.9) ; v1(145.91,136.68) U4.46
  LY3 w0.122: v1(147.45,102.9) 146.91,103.44 146.91,104.23 146.24,104.91 146.24,110.12 145.29,111.07 145.29,112.32 143.51,114.09 143.51,117.32 v1(144.77,118.58)
  LY12 w0.122: v1(145.91,136.68) 144.91,135.68 144.91,132.26 146.97,130.2 146.97,120.78 v1(144.77,118.58)
PM_DATA_6: length 42.7
  TOP w0.191: U4.48 v1(145.91,135.68) ; U15.M30 v1(147.45,103.9) ; U8.48 v1(144.47,117.58)
  LY3 w0.122: v1(144.47,117.58) 143.78,116.9 143.78,114.58 145.58,112.78 145.58,111.81 146.53,110.86 146.53,105.02 147.45,104.1 v1(147.45,103.9)
  LY12 w0.122: v1(144.47,117.58) 145.1,117.58 147.25,119.73 147.25,130.32 145.19,132.38 145.19,134.96 v1(145.91,135.68)
PM_DATA_7: length 45.9
  TOP w0.191: U8.50 v1(144.44,116.58) ; U15.N26 v1(148.45,99.9) ; v1(145.91,134.68) U4.50
  LY3 w0.076: 147.71,104.38 147.86,104.24 147.86,100.49
  LY3 w0.102: v1(148.45,99.9) 147.86,100.49
  LY3 w0.122: v1(144.44,116.58) 145.1,116.58 147.71,113.97 147.71,104.38
  LY12 w0.122: v1(144.44,116.58) 145.1,116.58 147.53,119.01 147.53,130.43 145.47,132.5 145.47,134.24 v1(145.91,134.68)
PM_DATA_8: length 53.8
  TOP w0.191: U15.N27 v1(148.45,100.9) ; U8.36 v1(144.4,123.58) ; U4.36 v1(145.91,141.68)
  LY3 w0.122: v1(144.4,123.58) 145.1,123.58 149.62,119.06 149.62,113.76 149.56,113.7 149.56,105.15 149.94,104.76 149.94,101.54 149.79,101.38 148.93,101.38 v1(148.45,100.9)
  LY12 w0.122: v1(144.4,123.58) 145.1,123.58 145.58,124.06 145.58,129.62 143.51,131.68 143.51,139.28 v1(145.91,141.68)
PM_DATA_9: length 49.4
  TOP w0.191: U8.38 v1(144.4,122.58) ; U4.38 v1(145.91,140.68) ; U15.N29 v1(148.45,102.9)
  LY3 w0.122: v1(148.45,102.9) 148.94,103.39 148.94,104.93 148.55,105.32 148.55,119.13 145.1,122.58 v1(144.4,122.58)
  LY12 w0.122: v1(144.4,122.58) 145.1,122.58 145.86,123.34 145.86,129.74 143.79,131.8 143.79,138.56 v1(145.91,140.68)
PM_DATA_10: length 47
  TOP w0.191: U4.40 v1(145.91,139.68) ; U15.N30 v1(148.45,103.9) ; U8.40 v1(144.38,121.58)
  LY3 w0.122: v1(148.45,103.9) 148.45,105.03 148.27,105.21 148.27,118.41 145.1,121.58 v1(144.38,121.58)
  LY12 w0.122: v1(144.38,121.58) 145.1,121.58 146.13,122.62 146.13,129.85 144.07,131.92 144.07,137.84 v1(145.91,139.68)
PM_DATA_11: length 50.8
  TOP w0.191: U15.P26 v1(149.45,99.9) ; v1(145.91,138.68) U4.42 ; U8.42 v1(144.39,120.58)
  LY3 w0.076: 148.05,104.4 148.04,104.38 148.04,100.62 148.3,100.36
  LY3 w0.102: v1(149.45,99.9) 148.99,100.36 148.3,100.36
  LY3 w0.122: v1(144.39,120.58) 145.1,120.58 147.99,117.69 147.99,104.73 148.05,104.67 148.05,104.4
  LY12 w0.122: v1(145.91,138.68) 144.35,137.12 144.35,132.03 146.41,129.97 146.41,121.9 145.1,120.58 v1(144.39,120.58)
PM_DATA_12: length 52.2
  TOP w0.191: U15.P27 v1(149.45,100.9) ; v1(140.02,119.38) 140.97,119.38 141.27,119.08 U8.45 ; U4.45 142.32,137.19 141.25,137.19 140.96,137.48 v1(140.02,137.48)
  LY3 w0.122: v1(140.02,119.38) 141.56,119.38 143.02,120.84 143.02,128.64 139.56,132.1 139.56,137.02 v1(140.02,137.48)
  LY12 w0.076: 147.95,101.27 147.86,101.36 147.86,104.09 147.61,104.34 147.61,104.46
  LY12 w0.102: 147.95,101.27 147.95,100.61 148.12,100.44 148.98,100.44 v1(149.45,100.9)
  LY12 w0.122: v1(140.02,119.38) 140.02,114.3 140.8,113.51 141.43,113.51 143.99,110.96 144.98,110.96 147.61,108.32 147.61,104.46
PM_DATA_13: length 44.6
  TOP w0.191: U15.P28 v1(149.45,101.9) ; U4.47 v1(141.07,136.18) ; U8.47 v1(141.02,118.08)
  LY3 w0.122: v1(141.07,136.18) 139.87,134.98 139.87,132.19 143.28,128.77 143.28,120.25 141.11,118.08 v1(141.02,118.08)
  LY12 w0.122: v1(149.45,101.9) 149.95,102.4 149.95,104.21 149.2,104.96 148.92,104.96 148.58,105.3 148.58,108.58 142.56,114.6 142.56,116.64 141.11,118.08 v1(141.02,118.08)
PM_DATA_14: length 42.2
  TOP w0.191: U15.P29 v1(149.45,102.9) ; U8.49 v1(141.02,117.08) ; v1(141.05,135.18) U4.49
  LY3 w0.122: v1(141.02,117.08) 141.11,117.08 143.55,119.52 143.55,128.9 140.17,132.28 140.17,134.7 140.65,135.18 v1(141.05,135.18)
  LY12 w0.122: v1(141.02,117.08) 141.11,117.08 142.28,115.92 142.28,114.49 148.25,108.52 148.25,105.23 148.92,104.56 148.92,103.43 v1(149.45,102.9)
PM_DATA_15: length 45.1
  TOP w0.191: U15.R26 v1(150.45,99.9) ; U4.51 141.24,134.18 v1(141.03,134.39) ; U8.51 v1(141.02,116.08)
  LY3 w0.122: v1(141.02,116.08) 141.11,116.08 143.82,118.79 143.82,131.6 v1(141.03,134.39)
  LY12 w0.076: 147.97,104.46 147.97,104.25 148.04,104.18 148.04,101.63 148.29,101.38
  LY12 w0.102: 148.29,101.38 149.77,101.38 150,101.15 150,100.35 v1(150.45,99.9)
  LY12 w0.122: 147.97,104.46 147.97,108.4 142,114.37 142,115.2 141.11,116.08 v1(141.02,116.08)
PM_OEZ: length 55
  TOP w0.191: U15.R29 v1(150.45,102.9) ; v1(140.18,142.15) 140.71,142.68 U4.34 ; U8.34 v1(140.34,124.58)
  LY3 w0.122: v1(140.34,124.58) 141.43,124.58 141.68,124.84 141.68,127.44 141.5,127.62 140.8,127.62 138.22,130.2 138.22,140.19 v1(140.18,142.15)
  LY12 w0.122: v1(140.34,124.58) 141.24,124.58 142.84,122.99 142.84,114.78 150.59,107.03 150.59,104.59 150.96,104.23 150.96,103.41 v1(150.45,102.9)
  BOTTOM w0.191: R94.2 141.69,124.58 v1(140.34,124.58)
PM_WEZ: length 63.1
  TOP w0.191: U8.13 v1(164.3,119.58) ; U4.13 163.25,137.68 v1(163.29,137.73)
  LY3 w0.076: 159.83,103.87 158.96,103 158.96,102.63 158.81,102.49 158.28,102.49 158.27,102.49 158.22,102.49 158.22,102.49 158.19,102.49 157.87,102.17 157.87,102.16 157.86,102.14 157.86,101.55 157.73,101.42
  LY3 w0.102: 157.73,101.42 157.13,101.42 156.98,101.27 156.98,100.51 156.83,100.36 156.25,100.36 155.99,100.1 155.99,99.69 155.73,99.42 151.87,99.42 151.45,99.85 151.45,104.46 ; 159.83,103.87 161.17,103.87 161.46,104.15 161.46,104.46
  LY3 w0.122: v1(163.29,137.73) 163.29,137.66 162.68,137.05 162.68,135.59 162.07,134.98 162.07,132.04 165.81,128.31 165.81,128.25 165.86,128.2 165.86,121.14 v1(164.3,119.58) 162.24,117.53 162.24,112.72 161.73,112.21 161.73,108.93 161.36,108.56 161.36,105.23 161.46,105.13 161.46,104.46 ; v1(151.45,104.47) 151.45,104.46
  BOTTOM w0.102: 151.45,104.46 R112.1
  BOTTOM w0.191: v1(164.3,119.58) 163.05,119.58 162.73,119.9 R98.2 ; v1(151.45,104.47) 151.45,104.46
PM_WEZ_T: length 2
  TOP w0.191: U15.R28 v1(150.45,101.9)
  BOTTOM w0.191: R112.2 151.21,102.67 v1(150.45,101.9)
PMD0_SPI_CIPO: length 19.4
  TOP w0.191: R772.1 56.82,64.14 56.38,64.58 54.1,64.58 53.49,63.97 53.11,63.97 50.34,61.2 44.37,61.2 43.3,60.13 R844.2
PMD0_SPI_CLK: length 22.5
  TOP w0.191: v1(61.91,62.09) 61.91,61.52 62.12,61.31 U555.2 ; R847.2 v1(50.18,53.97)
  LY3 w0.122: v1(50.18,53.97) 58.51,53.97 63.12,58.58 63.12,61.46 62.49,62.09 v1(61.91,62.09)
PMD0_SPI_COPI: length 17.7
  TOP w0.191: R840.2 50.42,59.93 54.68,64.19 56.21,64.19 57.08,63.32 60.14,63.32 60.6,62.86 60.6,62.22 62.02,60.81 U555.3
PMD0_SPI_CSZ: length 28.9
  TOP w0.191: v1(63.74,63.32) 64.38,62.69 64.38,60.48 64.2,60.31 U555.4 ; R850.2 v1(50.08,46.35)
  LY12 w0.122: v1(63.74,63.32) 63.74,58.98 60.78,56.02 59.74,56.02 v1(50.08,46.35)
PMD0_VREG: length 30.7
  TOP w0.191: v1(68.17,52.16) 68.17,52.33 68.64,52.81 68.64,52.96 68.7,53.01 68.7,53.43 68.4,53.72 68.4,54.59 U555.20 ; U555.31 73.55,59.31 v1(73.62,59.23) ; v1(64.18,65.44) 64.77,65.44 65.38,64.83 U555.47
  LY3 w0.635: v1(64.18,65.44) 67.07,62.55 70.3,62.55 v1(73.62,59.23) 70.28,55.89 70.28,52.82 69.62,52.16 v1(68.17,52.16)
  BOTTOM w0.191: C757.1 68.49,51.83 v1(68.17,52.16)
PMD1_SPI_CIPO: length 45.4
  TOP w0.191: R845.2 v1(44.25,56.52)
  LY3 w0.122: v1(16.55,57.78) 17.86,56.47 22.4,56.47 24.81,54.06 24.81,48.88 25.62,48.07 35.56,48.07 36.47,48.98 36.47,55.97 37.64,57.13 43.63,57.13 v1(44.25,56.52)
  BOTTOM w0.191: R789.1 v1(16.55,57.78)
PMD1_SPI_CLK: length 45
  TOP w0.191: R848.2 v1(50.18,51.44) ; U556.2 22.96,53.69 v1(21.44,55.21)
  LY3 w0.122: v1(21.44,55.21) 24.04,52.61 24.04,48.33 25.32,47.05 36.85,47.05 37.64,47.84 37.64,48.83 38.91,50.1 38.91,52.94 39.67,53.7 43.23,53.7 45.5,51.44 v1(50.18,51.44)
PMD1_SPI_COPI: length 33.6
  TOP w0.191: U556.3 22.87,53.19 21.68,54.38 21.32,54.38 20.7,55 v1(20.7,56.98) ; R841.2 v1(45.55,57.78)
  LY3 w0.122: v1(45.55,57.78) 31.02,57.78 30.04,58.76 27.07,58.76 25.04,56.73 22.73,56.73 22.48,56.98 v1(20.7,56.98)
PMD1_SPI_CSZ: length 7.3
  TOP w0.191: U556.4 22.89,52.69 22.88,52.7 22.78,52.7 22.73,52.76 22.52,52.76 v1(21.81,53.47) 21.3,53.97 R851.2
PMD1_VREG: length 36.7
  TOP w0.191: v1(26.51,57.29) 27.01,56.79 U556.45 ; v1(26.51,57.29) 26.01,56.79 U556.47 ; v1(26.51,57.29) U556.46 ; 33.99,52.19 33.96,52.16 33.96,51.8 33.84,51.69 ; 33.99,52.19 U556.32 ; 33.99,52.19 v1(34.31,52.51) ; U556.20 29.01,48.24 29.26,48.5 30.8,48.5 31.01,48.29 U556.24 31.01,46.53 31.37,46.17 31.44,46.17 31.51,46.1 v1(32.28,46.1) ; 33.84,51.69 33.96,51.57 33.96,51.37 33.77,51.18 U556.30 ; 33.84,51.69 U556.31
  LY3 w0.635: v1(26.51,57.29) 26.51,55.23 26.92,54.82 30.43,54.82 31.4,53.84 32.98,53.84 v1(34.31,52.51)
  LY12 w0.635: v1(34.31,52.51) 32.28,50.48 v1(32.28,46.1)
  BOTTOM w0.191: C778.1 v1(34.31,52.51)
PMD2_SPI_CIPO: length 70.8
  TOP w0.191: v1(44.4,53.98) 44.39,53.97 R846.2
  LY12 w0.122: v1(44.4,53.98) 43.1,55.28 43.1,58.91 51.38,67.19 51.38,73.59 62,84.21 62,101.91 64.11,104.02 69.9,104.02 71.32,105.44 v1(71.32,106.69)
  BOTTOM w0.191: R810.1 71.32,105.73 v1(71.32,106.69)
PMD2_SPI_CLK: length 68.2
  TOP w0.191: R849.2 v1(49.99,48.89) ; v1(70.54,103.28) 70.56,103.28 70.62,103.22 U557.2
  LY12 w0.122: v1(49.99,48.89) 53.51,52.42 53.51,73.67 63.47,83.63 63.47,100.4 65.34,102.27 68.93,102.27 69.26,102.6 69.95,102.6 70.56,103.21 70.56,103.28 v1(70.54,103.28)
PMD2_SPI_COPI: length 64.2
  TOP w0.191: U557.3 70.79,102.72 70.79,102.72 70.37,102.72 70.37,102.72 68.59,102.72 v1(68.53,102.77) ; R842.2 v1(45.45,55.88)
  LY12 w0.122: v1(45.45,55.88) 52.83,63.26 52.83,74.13 62.76,84.06 62.76,101.25 64.21,102.7 68.46,102.7 v1(68.53,102.77)
PMD2_SPI_CSZ: length 26.2
  TOP w0.191: R852.2 55.77,93.6 57.15,94.98 57.15,100.57 v1(58.04,101.46) ; U557.4 v1(70.58,102.22)
  LY3 w0.122: v1(58.04,101.46) 59.43,101.46 61.29,103.31 69.49,103.31 70.58,102.22 v1(70.58,102.22)
PMD2_VREG: length 41.5
  TOP w0.191: v1(77.21,94.24) 77.27,94.3 77.27,94.86 77.27,94.86 77.27,95.28 77.27,95.28 U557.20 ; 82.45,101.22 v1(82.46,101.2) 81.98,100.71 U557.30 ; 82.45,101.22 81.95,101.72 U557.32 ; 82.45,101.22 U557.31 ; v1(82.17,95.06) 79.57,95.06 79.27,95.36 U557.24 ; U557.45 75.27,106.35 74.95,106.66 v1(74.77,106.66) U557.46
  TOP w0.203: U557.47 74.27,106.46 74.47,106.66 v1(74.77,106.66)
  LY3 w0.635: v1(82.17,95.06) 80.11,95.06 79.29,94.24 v1(77.21,94.24) ; v1(82.46,101.2) 82.46,102.66 81.25,103.87 76.45,103.87 74.73,105.59 74.73,106.63 v1(74.77,106.66)
  LY12 w0.635: v1(82.46,101.2) 81.71,100.45 81.71,98.79 82.85,97.65 82.85,95.74 v1(82.17,95.06)
  BOTTOM w0.381: C792.1 75.33,107.98 75,107.65 75,107.29 74.77,107.05 v1(74.77,106.66)
PMD_INTZ: length 182.6
  TOP w0.191: U555.36 73.02,61.81 73.2,61.98 73.2,62.42 73.07,62.54 73.07,63.64 TP237.1 ; U15.AD26 v1(160.45,99.9)
  LY3 w0.076: 142.65,96.49 141.62,96.49 141.62,96.49 141.28,96.49 141.28,96.49 140.62,96.49 140.62,96.49 140.28,96.49 140.28,96.49 139.62,96.49 139.62,96.49 139.28,96.49 139.28,96.49 138.62,96.49 138.62,96.49 138.15,96.49 137.88,96.76
  LY3 w0.102: 137.88,96.76 137.88,96.76 135.88,96.76 ; 142.65,96.49 143.5,97.34 148.81,97.34 149.65,96.5 153.68,96.5 153.94,96.75 153.94,97.15 154.21,97.42 155.3,97.42 155.99,96.72 157.98,96.72 158.68,97.42 159,97.42 160.02,98.43 160.02,99.48 160.44,99.9 v1(160.45,99.9)
  LY3 w0.122: 135.88,96.76 135.51,96.76 135.28,96.54 133.3,96.54 132.36,97.48 129.35,97.48 128.47,96.61 118.96,96.61 118.08,97.48 115.3,97.48 114.44,98.34 96.2,98.34 92.93,101.61 89.95,101.61 87.88,103.68 v1(87.16,103.68) ; v1(34.54,61.63) 44.01,61.63 50.44,68.06 67.56,68.06 70.89,64.73 71.7,64.73 71.78,64.65 72.06,64.65 TP237.1
  LY12 w0.122: v1(87.16,103.68) 85.9,102.42 85.9,100.01 88.11,97.8 88.11,95.61 87.7,95.21 84.93,95.21 83.13,93.41 83.13,81.06 71.78,69.7 71.78,64.93 TP237.1
  BOTTOM w0.191: TP237.1 72.46,64.84 72.44,64.87 72.44,65.31 R767.1 ; v1(87.16,103.68) 86.7,104.14 R814.1 ; R793.1 33.34,60.93 34.01,61.6 34.51,61.6 v1(34.54,61.63)
PMIC_PWRGOOD: length 227.2
  TOP w0.191: U555.35 73.21,61.31 v1(73.96,62.06) 73.98,62.08 TP238.1 ; U13.2 88.31,28.89 88.06,29.15 88.06,30.74 89.12,31.81 89.91,31.81 R153.2 89.97,36.18 v1(92.84,39.05) U14.2 ; R807.1 v1(87.34,102.87)
  LY3 w0.122: v1(39.12,55.88) 42.27,55.88 43.36,54.79 47.6,54.79 49.58,52.82 61.26,52.82 62.4,53.96 65.45,53.96 67.1,52.31 67.1,50.16 67.61,49.65 73.97,49.65 76.5,52.18 76.5,59.52 v1(73.96,62.06) ; v1(78.41,44.92) 78.63,44.69 85.26,44.69 90.9,39.05 v1(92.84,39.05)
  LY12 w0.122: v1(78.41,44.92) 76.25,47.08 76.25,61.23 TP238.1 73.98,65.28 84.63,75.93 84.63,79.69 83.66,80.65 83.66,92.29 85.19,93.81 86.89,93.81 88.69,95.61 88.69,98.84 86.58,100.95 86.58,102.12 v1(87.34,102.87) 88.29,103.82 88.29,120.15 81.94,126.5 81.94,134.3 78.51,137.73 78.51,144.53 v1(76.33,146.72) 75.05,147.99 73.61,147.99 72.41,149.18 68.17,149.18 v1(67.64,149.72)
  BOTTOM w0.191: R764.1 73.96,63.52 TP238.1 ; U569.4 68.46,149.37 68.12,149.72 v1(67.64,149.72) ; R786.1 v1(39.12,55.88)
POSENSE: length 337.9
  TOP w0.191: U8.14 v1(160.5,120.08) ; v1(94.4,31.01) 94.61,30.8 U20.2 ; U15.AE27 v1(161.45,100.9) ; v1(75.36,62.85) 74.72,62.21 74.72,62.09 73.44,60.81 U555.34 ; R809.1 v1(87.36,100.97) ; U4.14 v1(160.42,138.18)
  LY3 w0.122: v1(94.4,31.01) 87.71,31.01 85.67,33.05 85.67,37.83 82.39,41.11 81.13,41.11 v1(78.42,43.81) 66.02,43.81 63.52,46.31 56.03,46.31 53.64,43.93 49.7,43.93 48.81,44.81 48.81,47.23 45.51,50.53 42.03,50.53 v1(39.86,52.7) ; v1(107.29,94.37) 95.7,94.37 94.43,95.64 92.12,95.64 91.54,96.22 89.91,96.22 89.1,97.04 89.1,99.23 v1(87.36,100.97) ; v1(160.5,120.08) 160.61,120.08 162.12,121.59 162.12,126.78 161.21,127.69 159.76,127.69 158.29,129.17 158.29,136.69 159.78,138.18 v1(160.42,138.18)
  LY12 w0.122: v1(160.5,120.08) 164.81,120.08 165.53,119.36 165.53,110.91 167.13,109.31 167.13,103.08 165.43,101.38 161.93,101.38 v1(161.45,100.9) ; v1(87.36,100.97) 89.2,99.13 89.2,94.62 87.73,93.15 85.39,93.15 84.04,91.8 84.04,88.55 85.14,87.46 85.14,72.79 77.34,64.99 77.34,64.93 TP239.1 77.21,63.66 79.93,60.94 79.93,45.32 v1(78.42,43.81) ; v1(103.68,138.77) 103.68,133.61 104.97,132.32 104.97,98.54 106.4,97.11 106.4,95.26 v1(107.29,94.37)
  BOTTOM w0.191: v1(75.36,62.85) R765.1 76.55,63.57 76.63,63.65 76.65,63.65 77.21,64.21 TP239.1 ; v1(103.68,138.77) 104.92,138.77 106.96,136.74 131.6,136.74 136.99,131.35 143.66,131.35 150.49,138.18 v1(160.42,138.18) 160.61,138.18 160.8,138 R86.2 ; R788.1 v1(39.86,52.7)
POSENSE_DRVZ: length 1.8
  TOP w0.191: U20.4 99.16,30.15 R43.2
POSENSE_LED: length 1.6
  TOP w0.191: R43.1 D8.1
PRIMARY_PU: length 2.6
  BOTTOM w0.191: J82.1 157.8,113.55 R869.1
PROJ_ON: length 159.8
  TOP w0.191: v1(94.34,35.19) 94.6,34.92 U19.2 ; U3.4 71.33,139.06 v1(71.14,139.25) ; U18.2 v1(81.78,29.21) ; v1(82.06,97.04) 83.7,97.04 83.89,96.85 U525.2 85.96,96.85 86.25,96.55 86.25,94.81 R886.2
  LY3 w0.122: v1(94.34,35.19) 94.6,34.92 95.66,34.92 96.31,34.27 96.31,30.34 95.04,29.07 87.68,29.07 87.53,29.21 v1(81.78,29.21)
  LY12 w0.122: v1(71.14,139.25) 71.33,139.06 71.33,130.94 73.12,129.14 77.31,129.14 78.74,127.72 78.74,105.24 79.68,104.3 79.68,99.42 v1(82.06,97.04) 79.68,94.65 79.68,86.27 80.51,85.43 80.51,82.18 76.75,78.42 76.75,75.85 70.02,69.12 70.02,62.65 71.22,61.45 71.22,56.5 73.61,54.11 73.61,46.85 74.7,45.75 74.7,36.29 v1(81.78,29.21)
PROJ_ON_1: length 12.7
  TOP w0.191: U565.4 60.96,146.69 61.24,146.41 61.41,146.41 62.56,145.27 62.56,142.15 63.78,140.93 63.78,137.42 64.04,137.16 U2.1
PROJ_ON_3: length 15.3
  TOP w0.191: U2.4 v1(61.3,139.06) ; U3.2 v1(73.93,138.11)
  LY3 w0.122: v1(61.3,139.06) 62.76,139.06 63.2,138.62 73.43,138.62 v1(73.93,138.11)
PROJ_ON_DRV: length 1.8
  TOP w0.191: U19.4 99.16,34.28 R42.2
PROJ_ON_LED: length 1.6
  TOP w0.191: R42.1 D7.1
PROJ_ON_OD: length 122.3
  TOP w0.191: U15.AG2 v1(163.45,74.9) ; U18.4 v1(86.27,28.56)
  LY3 w0.122: v1(86.27,28.56) 87.31,28.56 87.44,28.69 94.56,28.69 94.69,28.56 100.51,28.56 109.57,37.62 122.4,37.62 124.27,35.76 130.19,35.76 130.63,35.31 139.67,35.31 140.33,34.65 151.66,34.65 156.89,39.89 v1(158.97,39.89)
  LY12 w0.122: v1(158.97,39.89) 158.97,45.27 163.67,49.97 163.67,51.6 164.49,52.42 164.49,57.85 166.26,59.62 166.26,66.86 164.54,68.59 164.54,70.1 164.51,70.13 164.51,71.26 163.45,72.32 v1(163.45,74.9)
  BOTTOM w0.191: v1(86.27,28.56) 85.19,28.56 R125.2
PU.0: length 14.3
  TOP w0.191: U26.62 33.9,111.96 35.63,110.22 35.63,104.02 37.41,102.24 39.04,102.24 TP127.1
PU.1: length 11.7
  TOP w0.191: TP72.1 36.85,106.34 36.85,110.3 34.19,112.95 U26.64
PUR: length 14.9
  TOP w0.191: TP128.1 40.31,103.51 37.38,103.51 36.29,104.61 36.29,110.24 34.08,112.46 U26.63
PWM_BLU: length 10.3
  TOP w0.191: v1(131.48,53.38) U43.21
  LY12 w0.122: v1(131.48,53.38) 131.82,53.05 131.82,49.92 J97.5
PWM_GRN: length 10.9
  TOP w0.191: U43.22 v1(132.13,55.99)
  LY12 w0.122: v1(132.13,55.99) 132.13,54.11 133.82,52.42 133.82,50.49 133.78,50.45 133.78,49.96 J97.3
PWM_IN0: length 30
  LY12 w0.122: J73.3 114.8,92.98 114.17,93.61 114.17,98.87 J74.2
  BOTTOM w0.191: J77.1 121.6,81.48 120.62,82.46 120.62,86.55 119.45,87.72 117.89,87.72 J73.3
PWM_IN1: length 11.7
  LY12 w0.122: J73.4 113.3,92.76 J79.1 110.84,95.22 110.84,98.08 109.54,99.38 J74.1
PWM_IR: length 10.6
  TOP w0.191: U43.20 v1(130.83,53.91)
  LY12 w0.122: v1(130.83,53.91) 130.83,53.45 129.84,52.46 129.84,51.31 129.84,51.31 129.84,50.48 129.84,50.48 129.84,49.89 J97.9
PWM_OUT_BLED: length 49.9
  TOP w0.191: v1(131.16,61.91) 131.77,62.52 131.77,63.36 131.48,63.65 U43.4 ; U15.AF1 161.95,73.34 161.68,73.07 161.68,70.44 R643.1 162.28,69.7 162.28,68.54 161.54,67.8 158.34,67.8 158.03,67.48 158.03,65.13 156.18,63.28 v1(156.18,60.49)
  LY3 w0.122: v1(131.16,61.91) 131.16,59.7 131.92,58.94 134.51,58.94 135.15,59.57 155.27,59.57 v1(156.18,60.49)
PWM_OUT_GLED: length 161.4
  TOP w0.191: v1(165.48,70.77) 164.76,71.49 164.76,72.53 164.74,72.55 164.74,72.62 164.47,72.88 163.87,72.88 R644.1 162.15,72.11 162.15,72.7 162.51,73.07 162.51,74.84 U15.AF2 ; v1(131.9,66.13) 132.13,65.89 U43.3
  LY3 w0.122: v1(165.48,70.77) 164.84,70.14 164.84,68.33 164.41,67.9 161.69,67.9 158.52,64.73 158.52,62.67 158.19,62.34 157.58,62.34 155.93,63.99 151.33,63.99 149.3,61.96 147.09,61.96 145.94,63.1 135.86,63.1 134.26,64.7 132.2,64.7 131.9,65.01 v1(131.9,66.13) 131.24,66.79 130.6,66.79 126.72,62.91 126.72,62.9 123.34,59.52 120.24,59.52 119.22,60.54 119.22,63.41 117.78,64.86 109.62,64.86 108.94,64.17 105.89,64.17 104.19,65.87 104.19,67.95 102.99,69.15 v1(101.06,69.15)
  LY12 w0.122: v1(101.06,69.15) 100.05,70.16 100.05,89.19 101.85,90.99 101.85,97.04 102.31,97.49 102.31,117 97.47,121.84 J98.1
PWM_OUT_IRLED: length 50.5
  TOP w0.191: U43.5 v1(130.83,66.13) ; U15.AG3 v1(163.45,75.9)
  LY3 w0.122: v1(130.83,66.13) 130.83,64.93 131.34,64.42 134.16,64.42 135.77,62.81 142.35,62.81 143.53,61.63 v1(157.96,61.63)
  BOTTOM w0.191: v1(157.96,61.63) 157.1,62.49 157.1,63.89 162.29,69.09 162.29,70.52 162.91,71.15 162.91,75.37 v1(163.45,75.9) ; v1(130.83,66.13) 131.16,65.8 131.16,65.01 R642.1
PWM_OUT_RLED: length 39.8
  TOP w0.191: U43.2 v1(132.78,66.09)
  LY3 w0.122: v1(157.88,62.87) 156.33,64.42 150.95,64.42 148.87,62.34 147.08,62.34 146.06,63.37 135.97,63.37 133.25,66.09 v1(132.78,66.09)
  BOTTOM w0.191: v1(157.88,62.87) 157.88,63.46 158.26,63.84 158.26,64.51 161.78,68.03 162.33,68.03 J505.1 ; v1(132.78,66.09) 132.78,65.04 R645.1
